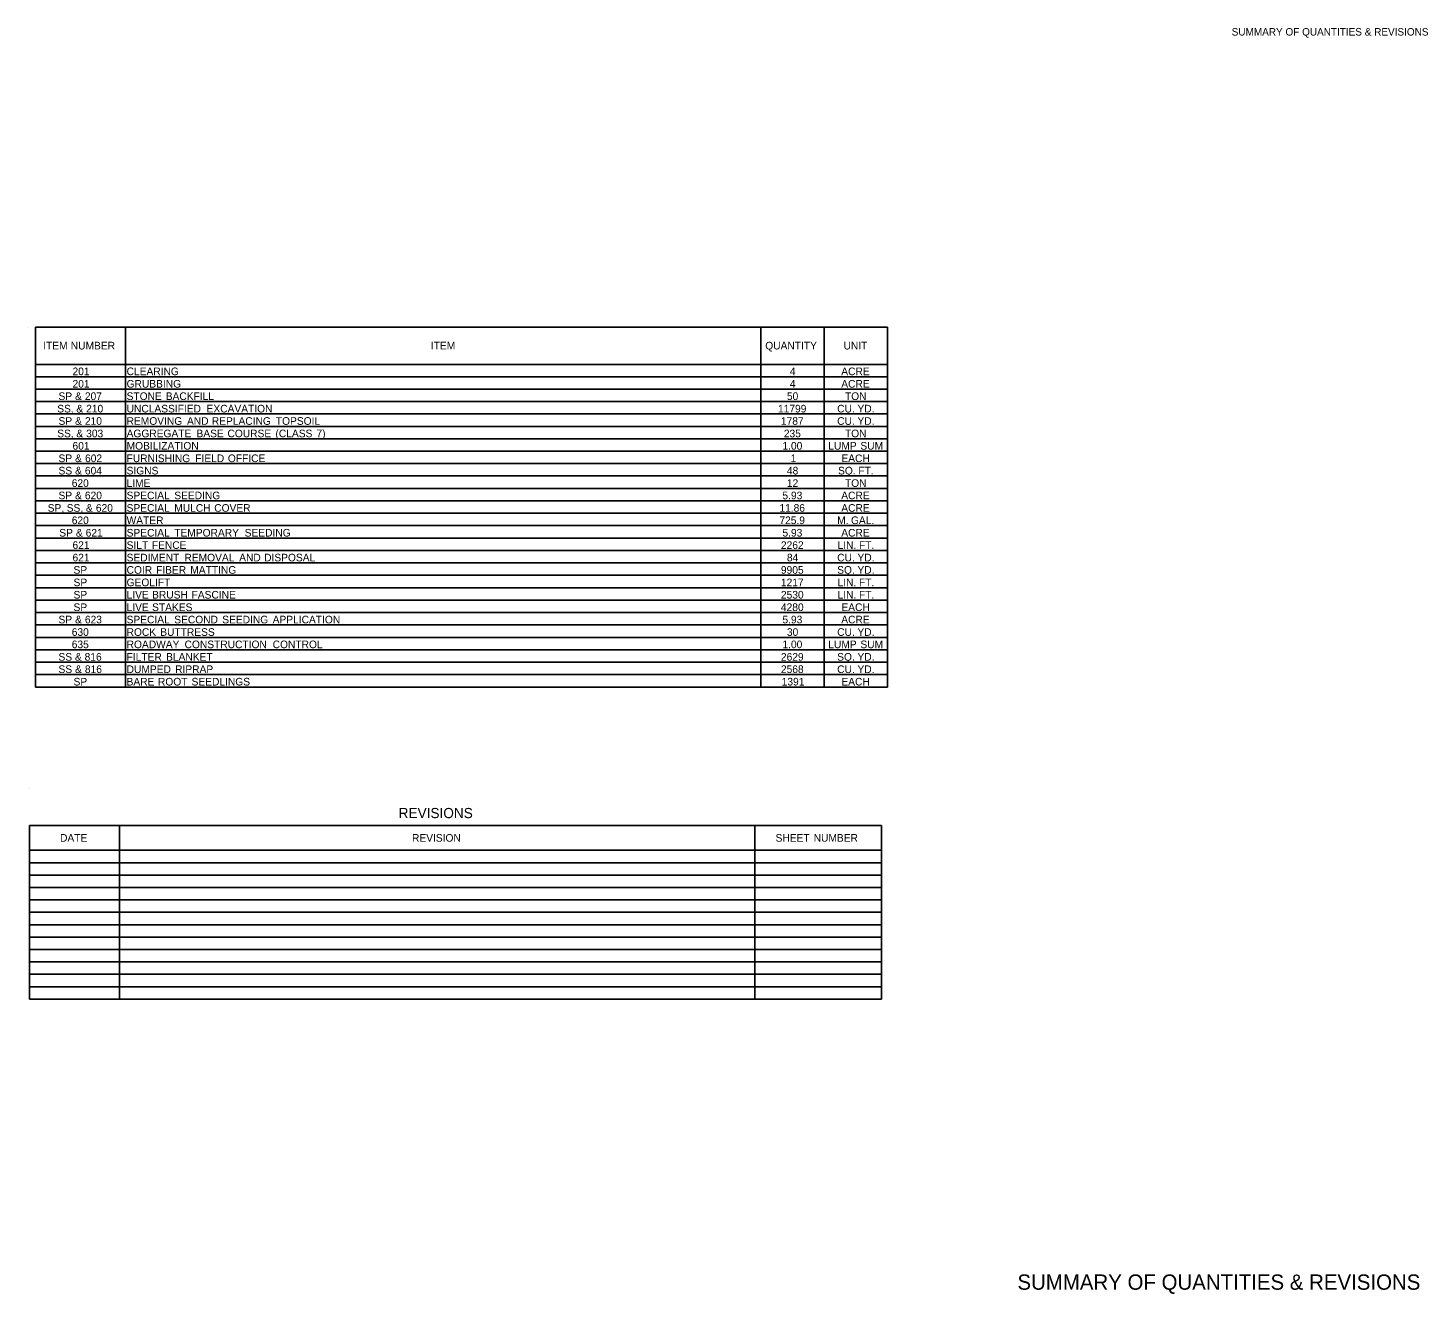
# Model space of a CAD drawing. Extents: x -2001791 to 62654501, y -2521700 to -592476.
# Drawn here: x -1997499 to -1996399, y -593470 to -592476 of the extents above; entities that cross this region are included whole.
import ezdxf

# ---------------------------------------------------------------- set-up
doc = ezdxf.new("R2010")
doc.units = 0
for name, color, linetype in [('Default', 7, 'Continuous'), ('R_Border', 7, 'Continuous'), ('R_Border Prem', 7, 'Continuous')]:
    doc.layers.add(name, color=color, linetype=linetype)

msp = doc.modelspace()

# ---------------------------------------------------------------- linework, layer by layer
at = {"layer": 'Default'}
for p, q in [((-1997492.7, -592710.5), (-1996823.4, -592710.5)), ((-1997492.7, -592993.3), (-1997492.7, -592710.5)), ((-1997492.7, -592993.3), (-1997492.7, -592710.5)), ((-1997422, -592993.3), (-1997422, -592710.5)), ((-1996922.8, -592993.3), (-1996922.8, -592710.5)), ((-1996873.1, -592993.3), (-1996873.1, -592710.5)), ((-1996873.1, -592925), (-1996873.1, -592710.5)), ((-1996823.4, -592993.3), (-1996823.4, -592710.5)), ((-1997492.7, -592739.8), (-1996823.4, -592739.8)), ((-1997422, -592895.8), (-1997422, -592739.8)), ((-1996922.8, -592925), (-1996922.8, -592739.8)), ((-1997492.7, -592749.5), (-1996823.4, -592749.5)), ((-1996873.1, -592749.5), (-1996823.4, -592749.5)), ((-1997492.7, -592759.3), (-1996823.4, -592759.3)), ((-1997492.7, -592769), (-1996823.4, -592769)), ((-1997492.7, -592778.8), (-1996823.4, -592778.8)), ((-1997492.7, -592788.5), (-1996823.4, -592788.5)), ((-1997492.7, -592798.3), (-1996823.4, -592798.3)), ((-1997492.7, -592808), (-1996823.4, -592808)), ((-1997492.7, -592817.8), (-1996823.4, -592817.8)), ((-1997492.7, -592827.5), (-1996823.4, -592827.5)), ((-1997492.7, -592837.3), (-1996823.4, -592837.3)), ((-1997492.7, -592847), (-1996823.4, -592847)), ((-1997492.7, -592856.8), (-1996823.4, -592856.8)), ((-1997492.7, -592866.5), (-1996823.4, -592866.5)), ((-1997492.7, -592876.3), (-1996823.4, -592876.3)), ((-1997492.7, -592886), (-1996823.4, -592886)), ((-1997492.7, -592895.8), (-1996823.4, -592895.8)), ((-1997422, -592925), (-1997422, -592895.8)), ((-1997492.7, -592905.5), (-1996823.4, -592905.5)), ((-1997492.7, -592915.3), (-1996823.4, -592915.3)), ((-1997492.7, -592925), (-1996873.1, -592925)), ((-1997492.7, -592925), (-1996922.8, -592925)), ((-1996922.8, -592925), (-1996823.4, -592925)), ((-1997492.7, -592934.8), (-1996823.4, -592934.8)), ((-1997422, -592983.5), (-1997422, -592934.8)), ((-1996922.8, -592934.8), (-1996873.1, -592934.8)), ((-1996922.8, -592993.3), (-1996922.8, -592934.8)), ((-1996873.1, -592934.8), (-1996823.4, -592934.8)), ((-1996873.1, -592993.3), (-1996873.1, -592934.8)), ((-1997492.7, -592944.5), (-1996823.4, -592944.5)), ((-1997492.7, -592954.3), (-1996823.4, -592954.3)), ((-1997492.7, -592964), (-1996823.4, -592964)), ((-1997492.7, -592973.8), (-1996823.4, -592973.8)), ((-1997492.7, -592983.5), (-1996823.4, -592983.5)), ((-1997492.7, -592993.3), (-1996823.4, -592993.3)), ((-1997422, -592993.3), (-1997422, -592983.5)), ((-1997497.5, -593102), (-1996828.2, -593102)), ((-1997497.5, -593102), (-1997426.8, -593102)), ((-1997497.5, -593238.5), (-1997497.5, -593102)), ((-1997426.8, -593238.5), (-1997426.8, -593102)), ((-1996927.6, -593102), (-1996828.2, -593102)), ((-1996927.6, -593121.5), (-1996927.6, -593102)), ((-1996927.6, -593238.5), (-1996927.6, -593102)), ((-1996828.2, -593238.5), (-1996828.2, -593102)), ((-1997497.5, -593121.5), (-1996828.2, -593121.5)), ((-1997497.5, -593131.3), (-1996828.2, -593131.3)), ((-1997497.5, -593141), (-1996828.2, -593141)), ((-1997497.5, -593150.8), (-1996828.2, -593150.8)), ((-1997497.5, -593160.5), (-1996828.2, -593160.5)), ((-1997497.5, -593170.3), (-1996828.2, -593170.3)), ((-1997497.5, -593180), (-1996828.2, -593180)), ((-1997497.5, -593189.8), (-1996828.2, -593189.8)), ((-1997497.5, -593199.5), (-1996828.2, -593199.5)), ((-1997497.5, -593209.3), (-1996828.2, -593209.3)), ((-1997497.5, -593219), (-1996828.2, -593219)), ((-1997497.5, -593228.8), (-1996828.2, -593228.8)), ((-1997497.5, -593238.5), (-1996828.2, -593238.5))]:
    msp.add_line(p, q, dxfattribs=at)
at = {"layer": 'R_Border'}
for p, q in [((-1997498.6, -592710.5), (-1997498.6, -592710.5)), ((-1997497.5, -593072.8), (-1997497.5, -593072.8))]:
    msp.add_line(p, q, dxfattribs=at)

# ---------------------------------------------------------------- texts
at = {"layer": 'Default'}
for s, height, p in [('ITEM', 6, (-1997486.6, -592728.1)), (' NUMBER', 6, (-1997467.2, -592728.1)), ('ITEM', 6, (-1997182.1, -592728.1)), ('QUANTITY', 6, (-1996919.4, -592728.1)), ('UNIT', 6, (-1996857.9, -592728.1)), ('201', 6, (-1997463.6, -592748.3)), ('CLEARING', 6, (-1997421.1, -592748.3)), ('4', 6, (-1996900.1, -592748.3)), ('ACRE', 6, (-1996859.7, -592748.3)), ('SP', 6, (-1997474.6, -592767.8)), ('201', 6, (-1997463.6, -592758.1)), (' &', 6, (-1997463.8, -592767.8)), (' 207', 6, (-1997456.1, -592767.8)), ('GRUBBING', 6, (-1997421.1, -592758.1)), ('STONE', 6, (-1997421.1, -592767.8)), (' BACKFILL', 6, (-1997392.6, -592767.8)), ('50', 6, (-1996902.4, -592767.8)), ('4', 6, (-1996900.1, -592758.1)), ('ACRE', 6, (-1996859.7, -592758.1)), ('TON', 6, (-1996856.8, -592767.8)), ('SS,', 6, (-1997475.6, -592777.6)), (' &', 6, (-1997462.8, -592777.6)), (' 210', 6, (-1997455.1, -592777.6)), ('UNCLASSIFIED', 6, (-1997421.1, -592777.6)), (' EXCAVATION', 6, (-1997360.5, -592777.6)), ('11799', 6, (-1996909.4, -592777.6)), ('CU.', 6, (-1996862.9, -592777.6)), (' YD.', 6, (-1996849.2, -592777.6)), ('SP', 6, (-1997474.6, -592787.3)), (' &', 6, (-1997463.8, -592787.3)), (' 210', 6, (-1997456.1, -592787.3)), ('REMOVING', 6, (-1997421.1, -592787.3)), (' AND', 6, (-1997375.9, -592787.3)), (' REPLACING', 6, (-1997356.4, -592787.3)), (' TOPSOIL', 6, (-1997306.1, -592787.3)), ('1787', 6, (-1996907.1, -592787.3)), ('CU.', 6, (-1996862.9, -592787.3)), (' YD.', 6, (-1996849.2, -592787.3)), ('SS,', 6, (-1997475.6, -592797.1)), (' &', 6, (-1997462.8, -592797.1)), (' 303', 6, (-1997455.1, -592797.1)), ('AGGREGATE', 6, (-1997421.1, -592797.1)), (' BASE', 6, (-1997368.4, -592797.1)), (' COURSE', 6, (-1997344.1, -592797.1)), (' (CLASS', 6, (-1997306.4, -592797.1)), (' 7)', 6, (-1997274.2, -592797.1)), ('235', 6, (-1996904.8, -592797.1)), ('TON', 6, (-1996856.8, -592797.1)), ('601', 6, (-1997463.6, -592806.8)), ('MOBILIZATION', 6, (-1997421.1, -592806.8)), ('1.00', 6, (-1996905.9, -592806.8)), ('LUMP', 6, (-1996869.9, -592806.8)), (' SUM', 6, (-1996846.9, -592806.8)), ('SP', 6, (-1997474.6, -592816.6)), (' &', 6, (-1997463.8, -592816.6)), (' 602', 6, (-1997456, -592816.6)), ('FURNISHING', 6, (-1997421.1, -592816.6)), (' FIELD', 6, (-1997369.4, -592816.6)), (' OFFICE', 6, (-1997343.8, -592816.6)), ('1', 6, (-1996899.5, -592816.6)), ('EACH', 6, (-1996859.6, -592816.6)), ('SS', 6, (-1997474.6, -592826.3)), (' &', 6, (-1997463.8, -592826.3)), (' 604', 6, (-1997456.1, -592826.3)), ('SIGNS', 6, (-1997421.1, -592826.3)), ('48', 6, (-1996902.4, -592826.3)), ('SQ.', 6, (-1996862.2, -592826.3)), (' FT.', 6, (-1996848.5, -592826.3)), ('620', 6, (-1997464.2, -592836.1)), ('LIME', 6, (-1997421.1, -592836.1)), ('12', 6, (-1996902.4, -592836.1)), ('TON', 6, (-1996856.8, -592836.1)), ('SP,', 6, (-1997483.1, -592855.6)), ('SP', 6, (-1997474.6, -592845.8)), (' SS,', 6, (-1997470.4, -592855.6)), (' &', 6, (-1997463.8, -592845.8)), (' 620', 6, (-1997456.1, -592845.8)), (' &', 6, (-1997455.3, -592855.6)), (' 620', 6, (-1997447.5, -592855.6)), ('SPECIAL', 6, (-1997421.1, -592845.8)), ('SPECIAL', 6, (-1997421.1, -592855.6)), (' SEEDING', 6, (-1997385.9, -592845.8)), (' MULCH', 6, (-1997385.9, -592855.6)), (' COVER', 6, (-1997354.5, -592855.6)), ('11.86', 6, (-1996908.3, -592855.6)), ('5.93', 6, (-1996905.9, -592845.8)), ('ACRE', 6, (-1996859.7, -592845.8)), ('ACRE', 6, (-1996859.7, -592855.6)), ('620', 6, (-1997464.2, -592865.3)), ('WATER', 6, (-1997421.1, -592865.3)), ('725.9', 6, (-1996908.3, -592865.3)), ('M.', 6, (-1996862.9, -592865.3)), (' GAL.', 6, (-1996854.3, -592865.3)), ('SP', 6, (-1997474, -592875.1)), (' &', 6, (-1997463.2, -592875.1)), (' 621', 6, (-1997455.5, -592875.1)), ('SPECIAL', 6, (-1997421.1, -592875.1)), (' TEMPORARY', 6, (-1997385.9, -592875.1)), (' SEEDING', 6, (-1997330.6, -592875.1)), ('5.93', 6, (-1996905.9, -592875.1)), ('ACRE', 6, (-1996859.7, -592875.1)), ('621', 6, (-1997463.6, -592884.8)), ('SILT', 6, (-1997421.1, -592884.8)), (' FENCE', 6, (-1997403.5, -592884.8)), ('2262', 6, (-1996907.1, -592884.8)), ('LIN.', 6, (-1996862.6, -592884.8)), (' FT.', 6, (-1996848, -592884.8)), ('621', 6, (-1997463.6, -592894.6)), ('SEDIMENT', 6, (-1997421.1, -592894.6)), (' REMOVAL', 6, (-1997377.9, -592894.6)), (' AND', 6, (-1997334.9, -592894.6)), (' DISPOSAL', 6, (-1997315.3, -592894.6)), ('84', 6, (-1996902.4, -592894.6)), ('CU.', 6, (-1996862.9, -592894.6)), (' YD.', 6, (-1996849.2, -592894.6)), ('SP', 6, (-1997462.8, -592904.3)), ('COIR', 6, (-1997421.1, -592904.3)), (' FIBER', 6, (-1997400.2, -592904.3)), (' MATTING', 6, (-1997373.3, -592904.3)), ('9905', 6, (-1996907.1, -592904.3)), ('SQ.', 6, (-1996862.9, -592904.3)), (' YD.', 6, (-1996849.2, -592904.3)), ('SP', 6, (-1997462.8, -592914.1)), ('GEOLIFT', 6, (-1997421.1, -592914.1)), ('1217', 6, (-1996907.1, -592914.1)), ('LIN.', 6, (-1996862.6, -592914.1)), (' FT.', 6, (-1996848, -592914.1)), ('SP', 6, (-1997462.8, -592923.8)), ('LIVE', 6, (-1997421.1, -592923.8)), (' BRUSH', 6, (-1997403.3, -592923.8)), (' FASCINE', 6, (-1997372.3, -592923.8)), ('2530', 6, (-1996907.1, -592923.8)), ('LIN.', 6, (-1996862.6, -592923.8)), (' FT.', 6, (-1996848, -592923.8)), ('SP', 6, (-1997474.6, -592943.3)), ('SP', 6, (-1997462.8, -592933.6)), (' &', 6, (-1997463.8, -592943.3)), (' 623', 6, (-1997456.1, -592943.3)), ('SPECIAL', 6, (-1997421.1, -592943.3)), ('LIVE', 6, (-1997421.1, -592933.6)), (' STAKES', 6, (-1997403.3, -592933.6)), (' SECOND', 6, (-1997385.9, -592943.3)), (' SEEDING', 6, (-1997348.2, -592943.3)), (' APPLICATION', 6, (-1997308.6, -592943.3)), ('4280', 6, (-1996907.1, -592933.6)), ('5.93', 6, (-1996905.9, -592943.3)), ('ACRE', 6, (-1996859.7, -592943.3)), ('EACH', 6, (-1996859.6, -592933.6)), ('630', 6, (-1997464.2, -592953.1)), ('ROCK', 6, (-1997421.1, -592953.1)), (' BUTTRESS', 6, (-1997396.9, -592953.1)), ('30', 6, (-1996902.4, -592953.1)), ('CU.', 6, (-1996862.9, -592953.1)), (' YD.', 6, (-1996849.2, -592953.1)), ('635', 6, (-1997464.2, -592962.8)), ('ROADWAY', 6, (-1997421.1, -592962.8)), (' CONSTRUCTION', 6, (-1997377.8, -592962.8)), (' CONTROL', 6, (-1997308.6, -592962.8)), ('1.00', 6, (-1996905.9, -592962.8)), ('LUMP', 6, (-1996869.9, -592962.8)), (' SUM', 6, (-1996846.9, -592962.8)), ('SS & 816', 6, (-1997474.6, -592972.6)), ('FILTER', 6, (-1997421.1, -592972.6)), (' BLANKET', 6, (-1997392.3, -592972.6)), ('2629', 6, (-1996907.1, -592972.6)), ('SQ.', 6, (-1996862.9, -592972.6)), (' YD.', 6, (-1996849.2, -592972.6)), ('SS', 6, (-1997474.6, -592982.3)), (' &', 6, (-1997463.8, -592982.3)), (' 816', 6, (-1997456.1, -592982.3)), ('DUMPED', 6, (-1997421.1, -592982.3)), (' RIPRAP', 6, (-1997385.2, -592982.3)), ('2568', 6, (-1996907.1, -592982.3)), ('CU.', 6, (-1996862.9, -592982.3)), (' YD.', 6, (-1996849.2, -592982.3)), ('SP', 6, (-1997462.8, -592992.1)), ('BARE', 6, (-1997421.1, -592992.1)), (' ROOT', 6, (-1997398.7, -592992.1)), (' SEEDLINGS', 6, (-1997372.3, -592992.1)), ('1391', 6, (-1996906.5, -592992.1)), ('EACH', 6, (-1996859.6, -592992.1)), ('REVISIONS', 8, (-1997207.4, -593096.3)), ('DATE', 6, (-1997473.4, -593114.8)), ('REVISION', 6, (-1997196.9, -593114.8)), ('SHEET', 6, (-1996911.3, -593114.8)), (' NUMBER', 6, (-1996883.6, -593114.8))]:
    msp.add_text(s, height=height, dxfattribs=at).set_placement(p)
at = {"layer": 'R_Border Prem'}
for height, p in [(5.862, (-1996553, -592481.5)), (12, (-1996721.3, -593466.8))]:
    msp.add_text('SUMMARY OF QUANTITIES & REVISIONS', height=height, dxfattribs=at).set_placement(p)

doc.saveas('drawing.dxf')
